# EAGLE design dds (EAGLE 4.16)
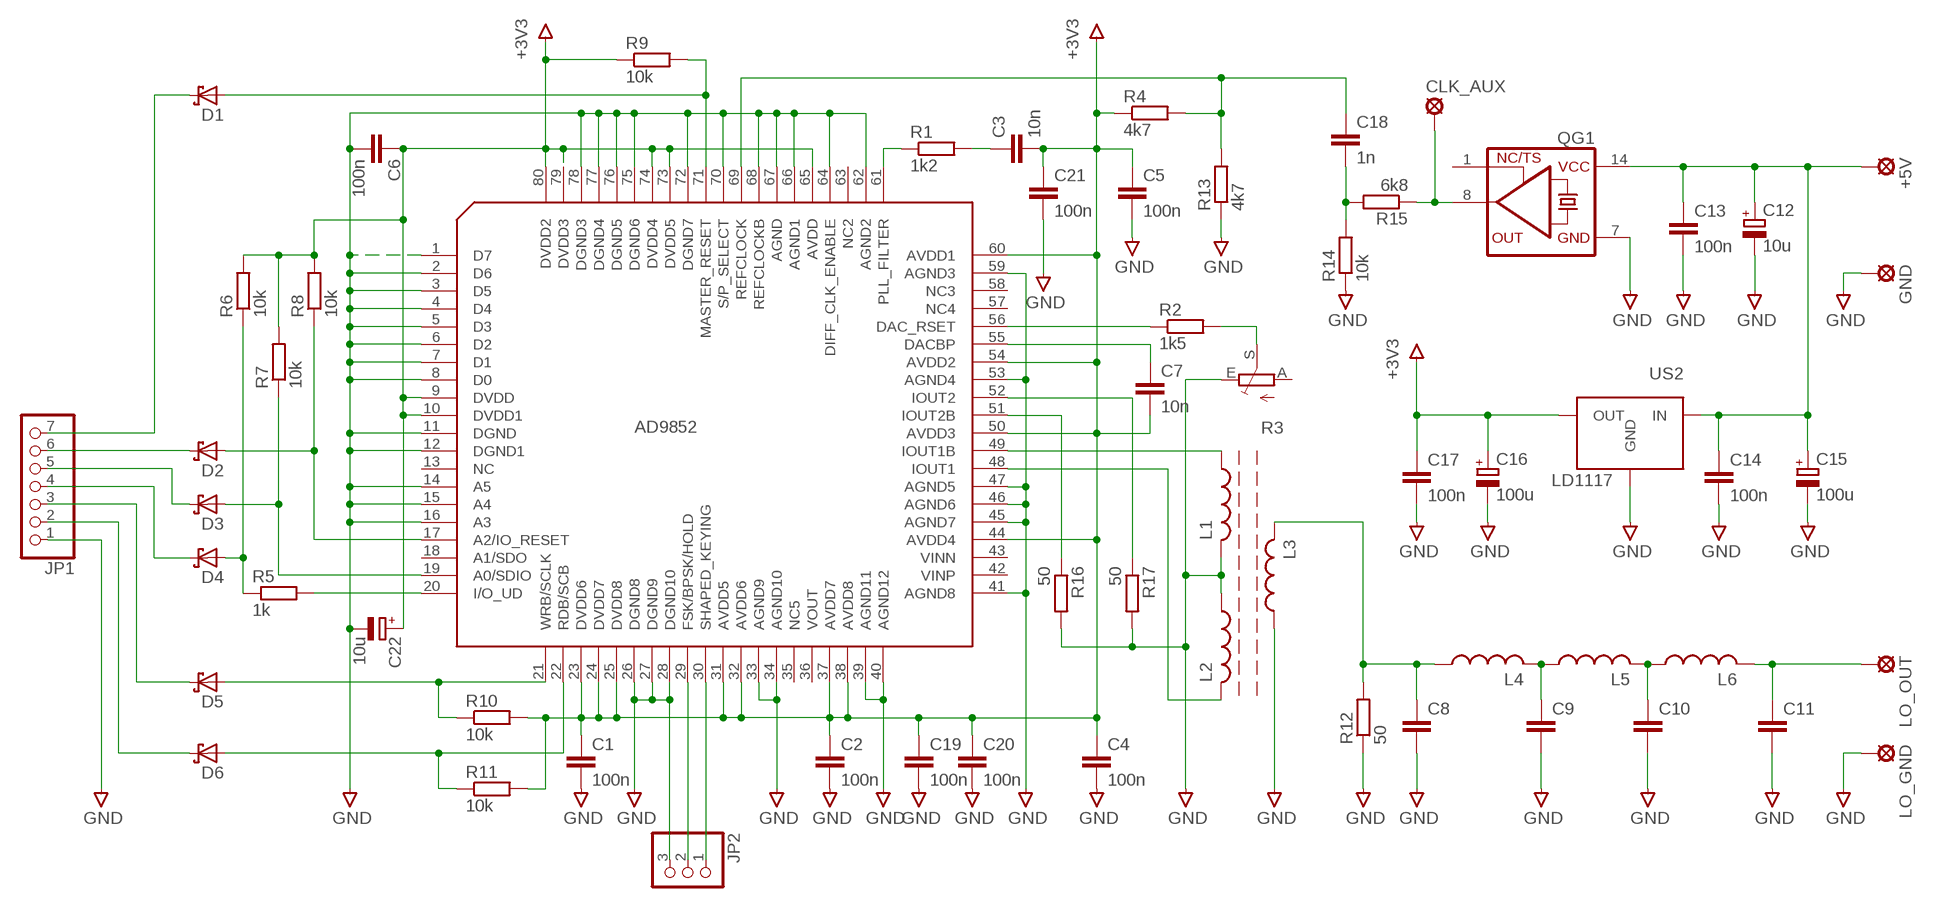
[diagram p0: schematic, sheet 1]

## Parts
+5V  LSP10  [LSP10]
C1  100n  C-EUC0805K  [C0805K]
C2  100n  C-EUC0805K  [C0805K]
C3  10n  C-EUC0805K  [C0805K]
C4  100n  C-EUC0805K  [C0805K]
C5  100n  C-EUC0805K  [C0805K]
C6  100n  C-EUC0805K  [C0805K]
C7  10n  C-EUC0805K  [C0805K]
C8  C-EU025-030X050  [C025-030X050]
C9  C-EU025-030X050  [C025-030X050]
C10  C-EU025-030X050  [C025-030X050]
C11  C-EU025-030X050  [C025-030X050]
C12  10u  CPOL-EUB45181A  [B45181A]
C13  100n  C-EU050-035X075  [C050-035X075]
C14  100n  C-EU050-035X075  [C050-035X075]
C15  100u  CPOL-EUB45181B  [B45181B]
C16  100u  CPOL-EUB45181B  [B45181B]
C17  100n  C-EU050-035X075  [C050-035X075]
C18  1n  C-EU025-030X050  [C025-030X050]
C19  100n  C-EUC0805K  [C0805K]
C20  100n  C-EUC0805K  [C0805K]
C21  100n  C-EUC0805K  [C0805K]
C22  10u  CPOL-EUB45181A  [B45181A]
CLK_AUX  LSP10  [LSP10]
D1  BAT42  [DO35-10]
D2  BAT42  [DO35-10]
D3  BAT42  [DO35-10]
D4  BAT42  [DO35-10]
D5  BAT42  [DO35-10]
D6  BAT42  [DO35-10]
GND  LSP10  [LSP10]
JP1  PINHD-1X7  [1X07]
JP2  PINHD-1X3  [1X03]
L1  L-US0204/5  [0204/5]
L2  L-US0204/5  [0204/5]
L3  L-US0204/5  [0204/5]
L4  L-US0204/5  [0204/5]
L5  L-US0204/5  [0204/5]
L6  L-US0204/5  [0204/5]
LO_GND  LSP10  [LSP10]
LO_OUT  LSP10  [LSP10]
QG1  XO-14  [DIL14S]
R1  1k2  R-EU_R1210  [R1210]
R2  1k5  R-EU_0207/12  [0207/12]
R3  TRIM_EU-CA6H  [CA6H]
R4  4k7  R-EU_0207/12  [0207/12]
R5  1k  R-EU_0207/12  [0207/12]
R6  10k  R-EU_0207/12  [0207/12]
R7  10k  R-EU_0207/12  [0207/12]
R8  10k  R-EU_0207/12  [0207/12]
R9  10k  R-EU_0207/12  [0207/12]
R10  10k  R-EU_0207/12  [0207/12]
R11  10k  R-EU_0207/12  [0207/12]
R12  50  R-EU_0207/12  [0207/12]
R13  4k7  R-EU_0207/12  [0207/12]
R14  10k  R-EU_0207/12  [0207/12]
R15  6k8  R-EU_0207/12  [0207/12]
R16  50  R-EU_0207/12  [0207/12]
R17  50  R-EU_0207/12  [0207/12]
U$1  AD9852  [SQ-80]
US2  LD1117  [TO-220]

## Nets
GND: C1.2 C2.2 C4.2 C5.2 C6.2 C8.2 C9.2 C10.2 C11.2 C12.- C13.2 C14.2 C15.- C16.- C17.2 C19.2 C20.2 C21.2 C22.- GND.MP JP1.1 JP2.3 L1.2 L2.1 L3.1 LO_GND.MP QG1.7(GND) R3.E R12.1 R13.1 R14.1 R16.2 R17.2 U$1.1(D7) U$1.2(D6) U$1.3(D5) U$1.4(D4) U$1.5(D3) U$1.6(D2) U$1.7(D1) U$1.8(D0) U$1.11(DGND) U$1.12(DGND1) U$1.14(A5) U$1.15(A4) U$1.16(A3) U$1.26(DGND8) U$1.27(DGND9) U$1.28(DGND10) U$1.33(AGND9) U$1.34(AGND10) U$1.39(AGND11) U$1.40(AGND12) U$1.41(AGND8) U$1.45(AGND7) U$1.46(AGND6) U$1.47(AGND5) U$1.53(AGND4) U$1.59(AGND3) U$1.62(AGND2) U$1.64(DIFF_CLK_ENABLE) U$1.66(AGND1) U$1.67(AGND) U$1.68(REFCLOCKB) U$1.70(S/P_SELECT) U$1.72(DGND7) U$1.75(DGND6) U$1.76(DGND5) U$1.77(DGND4) U$1.78(DGND3) US2.1(GND)
N$1: C7.1 U$1.55(DACBP)
N$2: L1.1 U$1.49(IOUT1B)
N$3: L2.2 U$1.48(IOUT1)
N$4: R2.1 U$1.56(DAC_RSET)
N$5: C3.1 R1.2
N$6: R1.1 U$1.61(PLL_FILTER)
N$7: R2.2 R3.S
N$8: R5.2 U$1.20(I/O_UD)
N$9: D1.A R9.2 U$1.71(MASTER_RESET)
N$10: D5.A R10.1 U$1.21(WRB/SCLK)
N$11: D6.A R11.1 U$1.22(RDB/SCB)
N$12: D2.A R8.1 U$1.17(A2/IO_RESET)
N$13: D3.A R7.1 U$1.19(A0/SDIO)
N$14: D4.A R5.1 R6.1
N$15: C8.1 L3.2 L4.1 R12.2
N$16: D1.C JP1.7
N$17: D2.C JP1.6
N$18: D3.C JP1.5
N$19: D4.C JP1.4
N$20: D5.C JP1.3
N$21: D6.C JP1.2
N$22: JP2.1 U$1.30(SHAPED_KEYING)
N$23: JP2.2 U$1.29(FSK/BPSK/HOLD)
N$24: C9.1 L4.2 L5.1
N$25: C10.1 L5.2 L6.1
N$26: C11.1 L6.2 LO_OUT.MP
N$27: +5V.MP C12.+ C13.1 C14.1 C15.+ QG1.14(VCC) US2.3(IN)
N$28: C18.1 R4.2 R13.2 U$1.69(REFCLOCK)
N$29: C18.2 R14.2 R15.2
N$30: CLK_AUX.MP QG1.8(OUT) R15.1
N$32: R16.1 U$1.51(IOUT2B)
N$33: R17.1 U$1.52(IOUT2)
N$51: C1.1 C2.1 C3.2 C4.1 C5.1 C6.1 C7.2 C16.+ C17.1 C19.1 C20.1 C21.1 C22.+ R4.1 R6.2 R7.2 R8.2 R9.1 R10.2 R11.2 U$1.9(DVDD) U$1.10(DVDD1) U$1.23(DVDD6) U$1.24(DVDD7) U$1.25(DVDD8) U$1.31(AVDD5) U$1.32(AVDD6) U$1.37(AVDD7) U$1.38(AVDD8) U$1.44(AVDD4) U$1.50(AVDD3) U$1.54(AVDD2) U$1.60(AVDD1) U$1.65(AVDD) U$1.73(DVDD5) U$1.74(DVDD4) U$1.79(DVDD3) U$1.80(DVDD2) US2.2(OUT) ; supply symbol labelled +3V3
Unconnected: QG1.1(TS) R3.A U$1.13(NC) U$1.18(A1/SDO) U$1.35(NC5) U$1.36(VOUT) U$1.42(VINP) U$1.43(VINN) U$1.57(NC4) U$1.58(NC3) U$1.63(NC2)

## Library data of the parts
+5V CLK_AUX GND LO_GND LO_OUT = solpad:LSP10: SOLDER PAD
C1-C7 C19-C21 = rcl-2:C-EU: CAPACITOR, European symbol
C8-C11 C13 C14 C17 C18 = rcl:C-EU: CAPACITOR, European symbol
C12 C15 C16 C22 = rcl:CPOL-EU: POLARIZED CAPACITOR, European symbol
D1-D6 = diode:BAT42: DIODE
JP1 = pinhead:PINHD-1X7: PIN HEADER
JP2 = pinhead:PINHD-1X3: PIN HEADER
L1-L6 = rcl:L-US: INDUCTOR, American symbol
QG1 = crystal:XO-: CRYSTAL
R1 = transceiver:R-EU_: RESISTOR, European symbol
R2 R4-R17 = rcl:R-EU_: RESISTOR, European symbol
R3 = pot:TRIM_EU-: POTENTIOMETER
U$1 = transceiver:AD9852
US2 = transceiver:LD1117

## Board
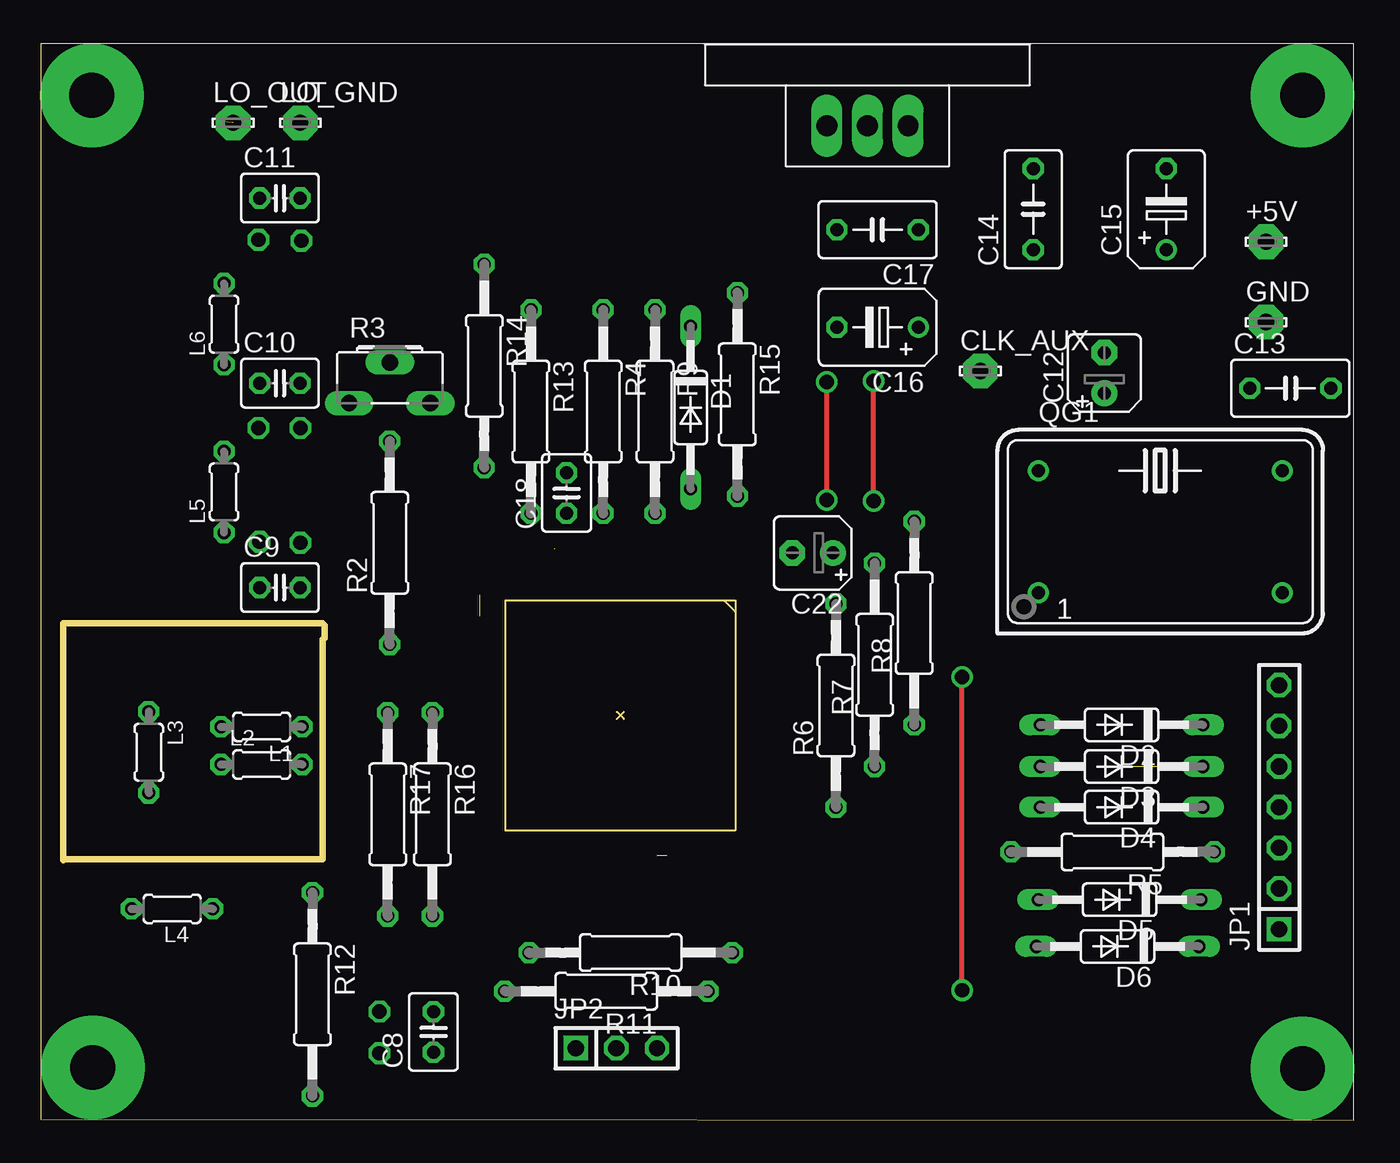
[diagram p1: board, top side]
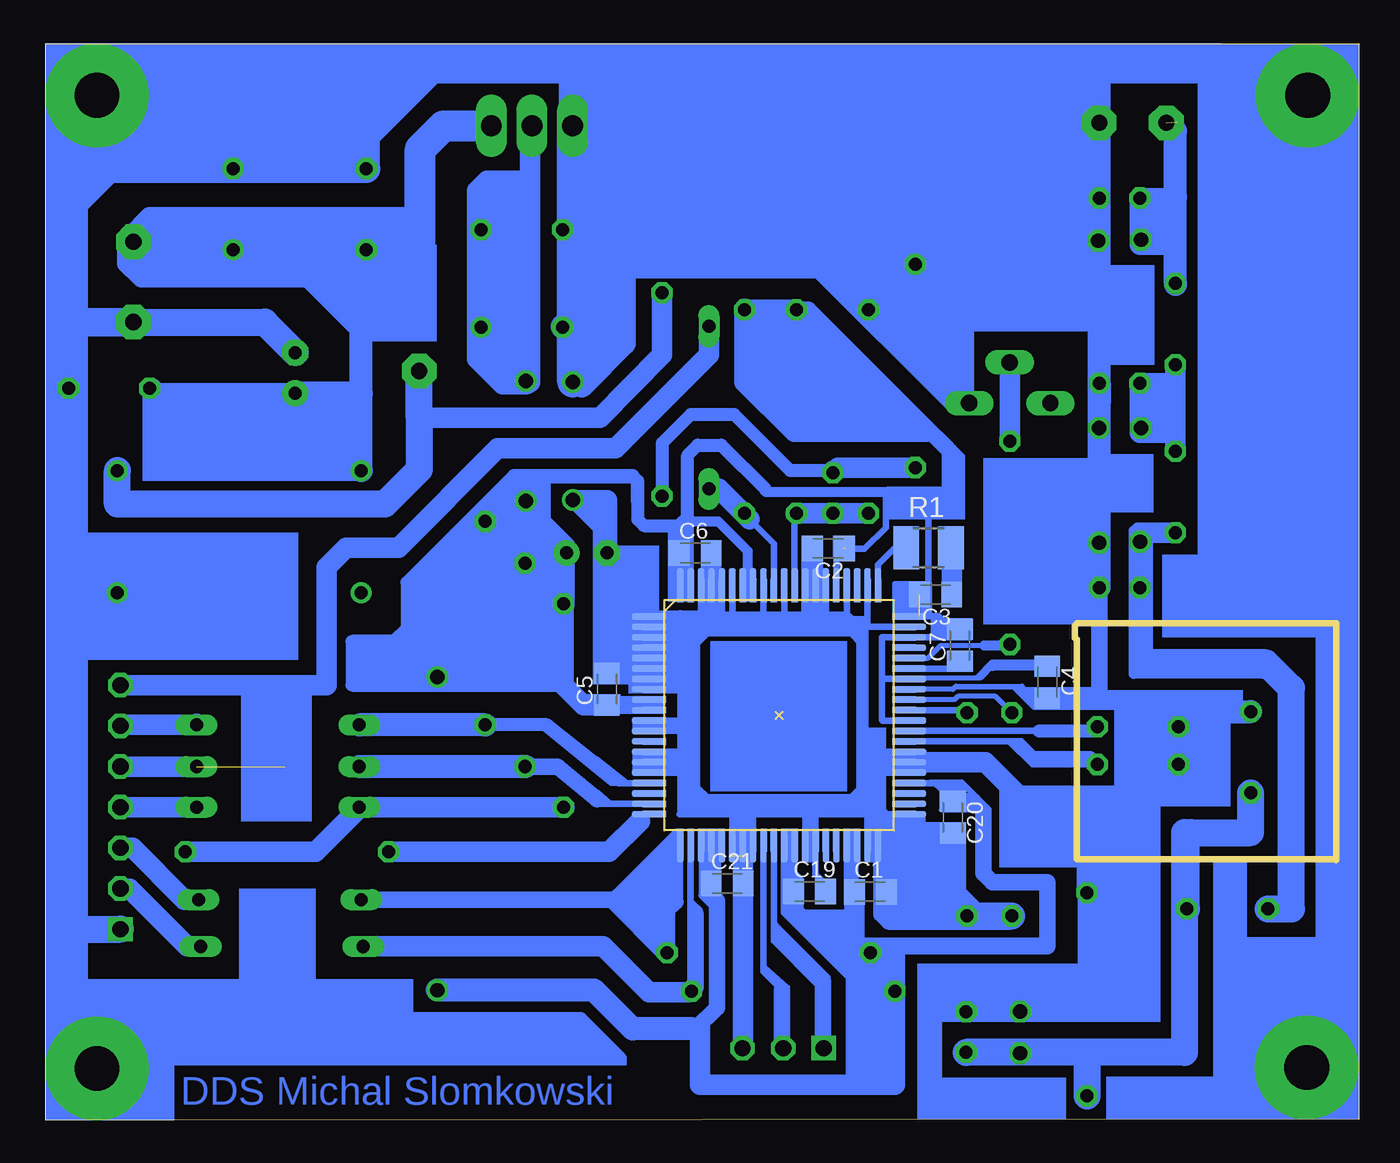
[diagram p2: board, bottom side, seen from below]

Size 82.03 x 67.24 mm. Coordinates in mm from the lower left corner, seen from the top.
Outline: 17.61,30.03 17.61,29.97
Outline: 17.61,29.97 17.61,16.31 1.49,16.31 1.42,16.25 1.42,31.05 17.61,31.05 17.74,30.92 17.74,30.09 17.61,29.97
Outline: 0,0.06 82.03,0 82.03,67.24 0,67.24 0,0.06
Copper layers (1*16): Top 0.035mm / dielectric 1.5mm / Bottom 0.035mm
Design rules "default": minimum track width 10mil, minimum drill 24mil, track to track 8mil, track to pad 8mil, pad to pad 8mil, via to via 8mil, smd to smd 8mil, copper to edge 40mil, drill to drill 8mil, minimum pad ring 10mil, minimum via ring 8mil, stop-mask expansion 4mil, vias tented up to drill 0mil, thermal gap 10mil

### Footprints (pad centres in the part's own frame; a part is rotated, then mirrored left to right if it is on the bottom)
LSP10 = drill 1.016 pad 2.159 octagon: MP 0,0
C0805K = smd 1.3 x 1.6: 1 -1,0; 2 1,0
C025-030X050 = drill 0.813 octagon: 1 -1.27,0; 2 1.27,0
B45181A = drill 0.813 pad 1.6 round: + -1.27,0 | drill 0.813 pad 1.6 octagon: - 1.27,0
C050-035X075 = drill 0.813 octagon: 1 -2.54,0; 2 2.54,0
B45181B = drill 0.813 round: + -2.54,0 | drill 0.813 octagon: - 2.54,0
DO35-10 = drill 0.813 long: A 5.08,0; C -5.08,0
1X07 = drill 1.016 square: 1 -7.62,0 | drill 1.016 octagon: 2 -5.08,0; 3 -2.54,0; 4 0,0; 5 2.54,0; 6 5.08,0; 7 7.62,0
1X03 = drill 1.016 square: 1 -2.54,0 | drill 1.016 octagon: 2 0,0; 3 2.54,0
0204/5 = drill 0.813 octagon: 1 -2.54,0; 2 2.54,0
DIL14S = drill 0.813 round: 1 -7.62,-3.81; 7 7.62,-3.81; 8 7.62,3.81; 14 -7.62,3.81
R1210 = smd 1.6 x 2.7: 1 -1.4,0; 2 1.4,0
0207/12 = drill 0.813 octagon: 1 -6.35,0; 2 6.35,0
CA6H = drill 1.016 long: A -2.54,0; E 2.54,0; S 0,2.54
SQ-80 = smd 0.813 x 0.406 bottom: 1 5.85,9.75; 2 5.85,9.1; 3 5.85,8.45; 4 5.85,7.8; 5 5.85,7.15; 6 5.85,6.5; 7 5.85,5.85; 8 5.85,5.2; 9 5.85,4.55; 10 5.85,3.9; 11 5.85,3.25; 12 5.85,2.6; 13 5.85,1.95; 14 5.85,1.3; 15 5.85,0.65; 16 5.85,0; 17 5.85,-0.65; 18 5.85,-1.3; 19 5.85,-1.95; 20 5.85,-2.6; 41 -11.7,-2.6; 42 -11.7,-1.95; 43 -11.7,-1.3; 44 -11.7,-0.65; 45 -11.7,0; 46 -11.7,0.65; 47 -11.7,1.3; 48 -11.7,1.95; 49 -11.7,2.6; 50 -11.7,3.25; 51 -11.7,3.9; 52 -11.7,4.55; 53 -11.7,5.2; 54 -11.7,5.85; 55 -11.7,6.5; 56 -11.7,7.15; 57 -11.7,7.8; 58 -11.7,8.45; 59 -11.7,9.1; 60 -11.7,9.75; P$1 -11.05,-2.6; P$2 -11.05,9.75; P$3 -10.4,9.75; P$22 -10.4,9.1; P$23 -10.4,8.45; P$25 -11.05,9.1; P$26 -11.05,8.45; P$27 -10.4,7.8; P$28 -11.05,7.15; P$29 -10.4,6.5; P$30 -10.4,5.85; P$31 -11.05,5.2; P$32 -10.4,4.55; P$33 -10.4,3.9; P$34 -10.4,3.25; P$35 -10.4,2.6; P$36 -10.4,1.95; P$37 -10.4,1.3; P$38 -10.4,0.65; P$39 -10.4,0; P$40 -10.4,-0.65; P$41 -10.4,-1.3; P$42 -10.4,-1.95; P$43 -10.4,-2.6; P$44 -11.05,7.8; P$45 -11.05,6.5; P$46 -10.4,7.15; P$47 -11.05,5.85; P$48 -10.4,5.2; P$49 -11.05,4.55; P$50 -11.05,3.9; P$51 -11.05,3.25; P$52 -11.05,2.6; P$53 -11.05,1.95; P$54 -11.05,1.3; P$55 -11.05,0.65; P$56 -11.05,0; P$57 -11.05,-0.65; P$58 -11.05,-1.3; P$59 -11.05,-1.95; P$121 4.55,-2.6; P$122 4.55,-1.95; P$123 4.55,-1.3; P$124 5.2,-2.6; P$125 5.2,-1.95; P$126 5.2,-1.3; P$127 4.55,-0.65; P$128 5.2,-0.65; P$129 4.55,0; P$130 5.2,0; P$131 4.55,0.65; P$132 5.2,0.65; P$133 4.55,1.3; P$134 5.2,1.3; P$135 4.55,1.95; P$136 5.2,1.95; P$137 4.55,2.6; P$138 5.2,2.6; P$139 4.55,3.25; P$140 5.2,3.25; P$141 4.55,3.9; P$142 5.2,3.9; P$143 4.55,4.55; P$144 5.2,4.55; P$145 4.55,5.2; P$146 5.2,5.2; P$147 4.55,5.85; P$148 5.2,5.85; P$149 5.2,6.5; P$150 4.55,6.5; P$151 4.55,7.15; P$152 5.2,7.15; P$153 5.2,7.8; P$154 4.55,7.8; P$155 4.55,8.45; P$156 5.2,8.45; P$157 5.2,9.1; P$158 4.55,9.1; P$159 4.55,9.75; P$160 5.2,9.75 | smd 0.406 x 0.813 bottom: 21 3.25,-5.2; 22 2.6,-5.2; 23 1.95,-5.2; 24 1.3,-5.2; 25 0.65,-5.2; 26 0,-5.2; 27 -0.65,-5.2; 28 -1.3,-5.2; 29 -1.95,-5.2; 30 -2.6,-5.2; 31 -3.25,-5.2; 32 -3.9,-5.2; 33 -4.55,-5.2; 34 -5.2,-5.2; 35 -5.85,-5.2; 36 -6.5,-5.2; 37 -7.15,-5.2; 38 -7.8,-5.2; 39 -8.45,-5.2; 40 -9.1,-5.2; 61 -9.1,12.35; 62 -8.45,12.35; 63 -7.8,12.35; 64 -7.15,12.35; 65 -6.5,12.35; 66 -5.85,12.35; 67 -5.2,12.35; 68 -4.55,12.35; 69 -3.9,12.35; 70 -3.25,12.35; 71 -2.6,12.35; 72 -1.95,12.35; 73 -1.3,12.35; 74 -0.65,12.35; 75 0,12.35; 76 0.65,12.35; 77 1.3,12.35; 78 1.95,12.35; 79 2.6,12.35; 80 3.25,12.35; P$4 -9.1,-3.9; P$5 -8.45,-3.9; P$6 -7.8,-3.9; P$7 -7.15,-3.9; P$8 -6.5,-3.9; P$9 -5.85,-3.9; P$10 -5.2,-3.9; P$11 -4.55,-3.9; P$12 -3.9,-3.9; P$13 -3.25,-3.9; P$14 -2.6,-3.9; P$15 -1.95,-3.9; P$16 -1.3,-3.9; P$17 -0.65,-3.9; P$18 0,-3.9; P$19 0.65,-3.9; P$20 1.3,-3.9; P$21 1.95,-3.9; P$24 2.6,-3.9; P$60 3.25,-3.9; P$81 -9.1,-4.55; P$82 -8.45,-4.55; P$83 -7.8,-4.55; P$84 -7.15,-4.55; P$85 -6.5,-4.55; P$86 -5.85,-4.55; P$87 -5.2,-4.55; P$88 -4.55,-4.55; P$89 -3.9,-4.55; P$90 -3.25,-4.55; P$91 -2.6,-4.55; P$92 -1.95,-4.55; P$93 -1.3,-4.55; P$94 -0.65,-4.55; P$95 0,-4.55; P$96 0.65,-4.55; P$97 1.3,-4.55; P$98 1.95,-4.55; P$99 2.6,-4.55; P$100 3.25,-4.55; P$181 3.25,11.05; P$182 2.6,11.05; P$183 1.95,11.05; P$184 3.25,11.7; P$185 2.6,11.7; P$186 1.95,11.7; P$187 1.3,11.7; P$188 0.65,11.7; P$189 0.65,11.05; P$190 1.3,11.05; P$191 0,11.7; P$192 0,11.05; P$193 -0.65,11.7; P$194 -0.65,11.05; P$195 -1.3,11.7; P$196 -1.3,11.05; P$197 -1.95,11.7; P$198 -1.95,11.05; P$199 -2.6,11.7; P$200 -2.6,11.05; P$201 -3.25,11.7; P$202 -3.25,11.05; P$203 -3.9,11.7; P$204 -3.9,11.05; P$205 -4.55,11.7; P$206 -4.55,11.05; P$207 -5.2,11.7; P$208 -5.2,11.05; P$209 -5.85,11.7; P$210 -5.85,11.05; P$211 -6.5,11.7; P$212 -6.5,11.05; P$213 -7.15,11.7; P$214 -7.15,11.05; P$215 -7.8,11.7; P$216 -7.8,11.05; P$217 -8.45,11.7; P$218 -8.45,11.05; P$219 -9.1,11.7; P$220 -9.1,11.05; P$224 -7.15,12.35; P$226 -6.5,12.35; P$228 -5.85,12.35; P$230 -5.2,12.35; P$233 -3.9,12.35; P$235 -3.25,12.35
TO-220 = drill 1.3 long: 1 -10.16,7.62; 2 -7.62,7.62; 3 -5.08,7.62

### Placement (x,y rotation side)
+5V  76.54,54.86 0 top
C1  30.52,14.26 0 bottom
C2  33.14,35.71 180 bottom
C3  26.44,32.82 180 bottom
C4  19.46,27.36 270 bottom
C5  46.97,26.93 90 bottom
C6  41.46,35.42 0 bottom
C7  24.92,29.66 90 bottom
C8  24.54,5.52 90 top
C9  14.95,33.27 0 top
C10  14.95,46.03 0 top
C11  14.95,57.59 0 top
C12  66.45,46.67 90 top
C13  78.07,45.72 0 top
C14  62,56.89 90 top
C15  70.32,56.89 90 top
C16  52.29,49.52 180 top
C17  52.29,55.62 180 top
C18  32.86,39.17 90 top
C19  34.32,14.28 0 bottom
C20  25.36,18.92 270 bottom
C21  39.46,14.79 0 bottom
C22  48.22,35.43 180 top
CLK_AUX  58.7,46.79 0 top
D1  40.6,44.51 270 top
D2  67.53,24.7 180 top
D3  67.53,22.09 180 top
D4  67.53,19.55 180 top
D5  67.4,13.77 180 top
D6  67.27,10.85 180 top
GND  76.54,49.84 0 top
JP1  77.37,19.55 90 top
JP2  35.97,4.5 0 top
L1  13.8,24.57 180 top
L2  13.8,22.22 0 top
L3  6.76,22.98 270 top
L4  8.22,13.2 180 top
L5  11.46,39.24 90 top
L6  11.46,49.72 90 top
LO_GND  16.22,62.29 0 top
LO_OUT  12.03,62.29 0 top
QG1  69.94,36.76 0 top
R1  26.89,35.75 0 bottom
R2  21.81,36.06 90 top
R3  21.81,44.79 0 top
R4  35.14,44.25 270 top
R5  66.95,16.76 180 top
R6  49.68,25.9 90 top
R7  52.1,28.44 90 top
R8  54.57,31.05 90 top
R9  38.38,44.25 270 top
R10  36.86,10.47 180 top
R11  35.33,8.06 180 top
R12  16.98,7.87 270 top
R13  30.63,44.25 270 top
R14  27.71,47.11 270 top
R15  43.52,45.33 270 top
R16  24.47,19.11 270 top
R17  21.68,19.11 270 top
U$1  39.14,21.71 0 top
US2  59.27,54.48 0 top

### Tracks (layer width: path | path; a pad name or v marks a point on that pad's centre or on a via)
GND  (via drill 0.9)  (1 unrouted)
  Top 0.305: v49.11,38.73 v49.11,46.1
  Bottom 0.254: 21.68,27.05 21.62,27.05 20.34,25.78 15.2,25.78
  Bottom 0.305: 25.37,26.91 25.23,27.05 21.68,27.05 21.49,27.05 21.43,27.05 | 25.37,26.91 U$1.53 | 25.37,26.91 25.17,27.11 21.04,27.11 20.15,26.22 12.73,26.22 | 11.27,24.76 L1.2 L2.1 11.27,22.09
  Bottom 0.406: 29.81,22.41 29.81,21.71 | 29.81,22.41 30.89,22.92 | 30.89,22.92 30.89,26.92 30.89,26.79 | 29.81,21.71 29.81,19.11 | 29.81,19.11 27.58,19.11 U$1.41 27.64,19.11 27.78,18.98 27.78,18.28 27.41,17.92 C20.2 | 29.81,21.71 U$1.45 | 30.89,22.92 29.49,22.98 29.65,23.01 U$1.47 | 29.81,22.41 29.74,22.41 29.69,22.36 27.97,22.36 U$1.46 | 29.81,19.11 29.74,19.11 | 29.81,19.11 30.06,19.11 | 30.06,19.11 30.7,19.11 | 42.38,19.11 42.44,19.11 | 42.38,19.11 42.38,21.71 | 42.38,21.71 42.38,22.41 | 42.38,22.41 42.38,23.05 | 42.38,23.05 42.38,24.32 | 42.38,24.32 42.38,25.01 | 42.38,25.01 42.38,26.92 | 42.38,26.92 42.38,27.62 | 42.38,27.62 42.38,28.19 | 42.38,28.19 42.38,28.82 | 42.38,28.82 42.38,29.52 | 42.38,29.52 42.38,30.16 | 42.38,30.16 42.38,30.79 | 42.38,30.79 42.38,31.43 42.32,31.49 42.32,31.55 | U$1.1 42.41,31.46 42.32,31.55 | U$1.2 42.4,30.81 42.38,30.79 | U$1.3 42.39,30.16 42.38,30.16 | U$1.4 42.39,29.51 42.38,29.52 | U$1.5 42.42,28.86 42.38,28.82 | U$1.6 44.48,28.21 42.4,28.21 42.38,28.19 | U$1.7 42.44,27.56 42.38,27.62 | U$1.8 42.39,26.91 42.38,26.92 | U$1.11 42.43,24.96 42.38,25.01 | U$1.12 42.38,24.31 42.38,24.32 | U$1.14 42.41,23.01 42.38,23.05 | U$1.15 42.43,22.36 42.38,22.41 | 42.38,21.71 U$1.16 | U$1.40 30.04,19.09 30.06,19.11 | 30.7,19.11 33.93,19.11 | 33.93,19.11 37.74,19.11 | 37.74,19.11 38.44,19.11 | 38.44,19.11 39.08,19.11 | 39.08,19.11 42.38,19.11 | U$1.34 33.93,16.51 33.93,19.11 | U$1.39 30.69,19.1 30.7,19.11 | 30.7,19.11 34.51,19.11 34.57,19.04 34.57,16.44 34.59,16.46 | 34.59,16.46 U$1.33 | 42.32,31.55 41.05,31.55 | 41.05,31.55 40.41,31.55 | 40.41,31.55 39.78,31.55 | 39.78,31.55 39.2,31.55 | 39.2,31.55 39.14,31.55 U$1.75 39.14,34.16
  Bottom 0.406: U$1.62 30.69,32.07 30.7,32.06 30.7,31.05 31.2,31.17 | 31.2,31.17 31.33,31.05 31.97,31.55 | 39.2,31.55 37.17,31.55 | 37.17,31.55 35.9,31.55 | 35.9,31.55 34.57,31.55 | 34.57,31.55 33.93,31.55 | 33.93,31.55 33.3,31.55 | 33.3,31.55 31.97,31.55 | U$1.64 31.99,31.58 31.97,31.55 | U$1.66 33.29,31.56 33.3,31.55 | U$1.67 33.94,31.56 33.93,31.55 | U$1.68 34.59,31.58 34.57,31.55 | U$1.72 37.19,31.57 37.17,31.55 | U$1.70 35.89,31.57 35.9,31.55 | U$1.78 41.09,31.6 41.05,31.55 | U$1.77 40.44,32.06 40.44,31.58 40.41,31.55 | U$1.76 39.79,31.57 39.78,31.55 | U$1.26 39.14,19.04 39.08,19.11 | 38.49,18.47 38.49,19.06 38.44,19.11 | U$1.28 37.84,19.01 37.74,19.11 | 34.59,16.46 34.08,16.46 33.93,16.31 33.93,15.36 33.36,14.79 33.36,14.35 33.3,14.28 C19.2 | U$1.59 30.91,30.81 31.2,31.17 | 27.46,21.84 27.46,21.97 | 20.41,26.35 20.73,26.35 21.43,27.05 | 21.49,27.05 20.47,26.03 20.03,26.03
  Bottom 0.61: U$1.46 27.44,21.86 27.46,21.84 | C4.2 19.64,26.36 19.65,26.35 20.41,26.35
  Bottom 0.813: C2.2 34.14,35.73 34.12,35.75 33.94,35.56 U$1.67 | C1.2 29.74,14.26 29.74,17.78 29.74,19.11
  Bottom 1.016: 44.48,28.21 44.48,28 44.55,27.93 C5.2 | 16.22,26.36 11.72,26.36 11.33,25.2 | 16.22,26.36 C4.2 | 16.22,26.36 16.22,26.35 | 16.22,26.36 C9.2
  Bottom 1.27: 40.44,32.06 40.35,32.06 40.46,32.17 C6.2 | 38.49,18.47 38.51,18.47 38.46,18.43 C21.2 38.46,4.46 | C22.- 46.95,38.73 48.98,38.73 | 48.98,38.73 v49.11,38.73 | 38.46,4.46 JP2.3 | 38.46,4.46 38.44,4.44 | 49.11,55.56 49.17,55.56 49.24,55.62 C17.2 | 49.11,49.33 49.37,49.33 49.56,49.52 C16.- | 17.23,20.25 16.98,20.25 R12.1 16.92,14.22 16.85,14.16 16.92,14.09 16.92,6.79 v21.17,6.79 C8.2 | 17.23,20.25 21.23,20.25 23.33,22.35 27.9,22.35 27.97,22.28 27.97,22.36 | 11.27,20.51 11.27,20.25 17.17,20.25 17.23,20.19 17.23,20.25 | L1.2 11.27,24.82 11.33,24.89 10.69,25.52 10.38,25.52 | 48.98,38.73 48.86,38.73 47.02,36.89
  Bottom 1.422: C16.- 49.75,49.59 | R13.1 30.63,50.67 24.75,44.79 R3.E 24.35,44.77 | L1.2 11.33,24.57 | 10.38,25.52 L3.1 | 10.76,24.63 11.33,25.2 | LO_GND.MP 16.28,62.29 16.22,62.23 C11.2 C10.2 | C10.2 16.22,44.76 | C9.2 v16.22,36.06 v16.22,43.24 C10.2 | 49.17,46.03 48.54,45.84 45.87,48.51 45.87,52.95 47.71,52.95 48.03,52.64 48.03,47.68 47.9,47.56 47.27,47.56 46.89,47.94 46.89,52.06 46.83,52.13
  Bottom 1.676: C22.- 46.95,28.57 45.36,28.57 45.05,28.89 45.02,28.86 U$1.5 | C13.2 80.61,36.06 | JP1.1 79.91,11.93 80.61,12.63 80.61,36.06 | QG1.7 80.54,32.95 80.61,36.06 | GND.MP 68.35,49.84 C12.- | C14.2 62,61.46 57.68,65.78 49.75,65.78 49.11,65.15 49.11,62.35 48.92,62.16 48.98,62.1 US2.1 | R14.1 28.66,54.29 30.63,54.29 | 30.63,54.29 48.98,54.29 49.11,56.07 | 30.63,54.29 30.63,50.67 | R17.2 R16.2 24.47,13.2 28.85,17.58 29.23,17.58 29.43,17.78 29.74,17.78 | L1.2 L2.1 11.27,20.51 | 10.76,24.63 10.38,24.63 11.27,24.76
  Bottom 1.778: 80.61,49.84 C13.2 | 80.61,49.84 80.61,56.95 78.13,59.43 C15.- C14.2 | 80.61,49.84 GND.MP
  Bottom 1.93: US2.1 49.11,56.07 49.11,55.56 49.11,49.33 v49.11,46.1
N$1
  Bottom 0.406: C7.1 25.11,28.69 25.36,28.76 25.26,28.21 U$1.55
N$2
  Bottom 0.406: U$1.49 19.97,24.31 19.96,24.32
  Bottom 0.813: L1.1 16.34,24.51 16.54,24.32 19.96,24.32
N$3
  Bottom 0.406: U$1.48 21.09,23.66 20.09,22.66
  Bottom 0.813: 20.09,22.66 16.79,22.66 L2.2
N$4
  Bottom 0.305: U$1.56 26.91,28.86 26.12,29.65 23.39,29.65
  Bottom 0.61: R2.1 21.87,29.71 21.93,29.65 23.39,29.65
N$5
  Bottom 1.016: 25.44,35.86 25.49,35.81 R1.2 | C3.1 25.44,35.86 | 25.44,35.86 25.43,35.87
N$6
  Bottom 0.406: U$1.61 30.04,34.69 28.98,35.75 R1.1 | R1.1 | R1.1 28.22,35.68
N$7
  Bottom 1.27: R3.S 21.77,47.33 21.74,47.3 21.81,47.24 R2.2
N$8
  Bottom 0.305: U$1.20 44.99,18.99 44.79,18.47
  Bottom 0.61: 44.79,18.47 44.92,18.66 45.49,18.28
  Bottom 1.27: R5.2 46.83,16.76 44.92,18.66
N$9
  Bottom 0.406: R9.2 38.12,37.59 36.54,36 U$1.71
  Bottom 1.27: R9.2 38.06,37.52 38.12,37.59 39.97,39.43 D1.A
N$10
  Bottom 0.406: U$1.21 42.39,13.95 43.2,13.65
  Bottom 1.016: R10.1 43.2,13.65 42.7,13.65 42.76,13.77 D5.A
N$11
  Bottom 0.406: U$1.22 41.74,12.82 41.43,12.89
  Bottom 1.016: 41.81,8.06 41.87,8 | R11.1 41.81,8.06 | 41.43,12.89 41.43,8.31 41.81,8.06
  Bottom 1.27: 41.87,8 44.35,8 47.21,10.85 D6.A
N$12
  Bottom 0.406: U$1.17 46.24,21.06 47.84,22.41
  Bottom 0.813: R8.1 50.7,24.7 47.84,22.41
  Bottom 1.422: R8.1 D2.A
N$13
  Bottom 0.406: U$1.19 47.42,19.76 47.59,20.06
  Bottom 1.016: 52.03,22.09 50.06,22.09 47.59,20.06
  Bottom 1.422: 52.03,22.09 R7.1 D3.A
N$14
  Bottom 1.27: R5.1 65.18,16.76 62.45,19.49 D4.A R6.1 49.62,19.55
N$15
  Bottom 1.676: L3.2 6.76,17.97 10.5,17.97 10.66,17.74 | 10.66,17.74 10.82,17.58 10.82,13.14 L4.1 | 16.85,4.25 10.88,4.25 10.88,17.97 10.66,17.74 | 16.85,4.25 C8.1 | 10.66,17.74 | R12.2 16.98,4.12 16.85,4.25
N$16
  Bottom 1.27: JP1.7 77.37,27.11 77.31,27.17 64.48,27.17 64.48,34.54 63.27,35.75 59.97,35.75 53.81,41.97 46.44,41.97 40.6,47.81 D1.C
N$17
  Bottom 1.27: D2.C 72.61,24.76 72.67,24.7 77.31,24.7
  Bottom 1.422: JP1.6 77.31,24.7
N$18  (1 unrouted)
  Bottom 1.27: JP1.5 D3.C
N$19
  Bottom 1.27: JP1.4 D4.C
N$20
  Bottom 1.27: JP1.3 76.61,17.01 73.37,13.77 D5.C
N$21
  Bottom 1.27: JP1.2 76.8,14.47 73.18,10.85 D6.C
N$22
  Bottom 0.406: U$1.30 36.54,11.75 35.2,10.41
  Bottom 1.016: 35.2,10.41 33.49,8.69 33.49,4.5 33.43,4.44 JP2.1
N$23
  Bottom 0.406: U$1.29 37.19,9.28 36.03,8.12
  Bottom 1.016: JP2.2 35.97,4.57 36.03,4.63 36.03,8.12
N$24  (via drill 0.9)
  Bottom 1.27: 13.49,28.57 13.49,36.57 C9.1 v13.68,36.13 13.68,36.7 L5.1
  Bottom 1.676: L4.2 4.22,13.2 4.22,26.98 5.8,28.57 13.49,28.57
N$25
  Bottom 1.27: L5.2 11.45,44.76 | 11.45,44.76 L6.1 | 11.45,44.76 11.52,46.03 C10.1 13.68,42.92 11.77,42.92
  Bottom 1.422: 11.77,42.92 12.73,43.87 12.73,44.25 12.6,44.38 12.6,45.14 12.54,45.21
N$26  (1 unrouted)
  Bottom 1.27: 11.45,57.65 11.45,57.59 C11.1 13.68,54.67 11.58,54.67 11.52,54.61 11.96,54.61 12.85,55.49 12.85,55.56 12.66,55.75 12.66,56.76
  Bottom 1.422: 11.45,52.19 L6.2 11.45,57.65 11.45,61.78 12.03,62.35 LO_OUT.MP
N$27
  Bottom 1.27: C14.1 62,54.41 62.32,54.1 | C13.1 75.4,45.72 75.08,45.4 66.32,45.4
  Bottom 1.422: 62.32,45.4 66.32,45.4 C12.+ | QG1.14 62.32,45.4 | 62.32,45.4 62.32,54.29 62.38,54.35
  Bottom 1.93: US2.3 57.17,62.1 58.64,60.64 58.64,54.35 C14.1 | C14.1 62.06,54.35 | C14.1 62.38,54.35 C15.+ 76.03,54.35 +5V.MP
N$28
  Bottom 0.406: U$1.69 35.24,37.87 35.2,37.9
  Bottom 1.27: R13.2 32.98,37.9 | 32.98,37.9 R4.2 | 32.98,37.9 35.2,37.9 C18.1
N$29
  Bottom 0.813: 32.86,40.57 35.52,40.57 39.02,44.06 41.75,44.06 43.52,42.29 R15.2 43.46,38.92
  Bottom 1.27: R14.2 32.54,40.76 32.79,40.51 | 32.79,40.51 C18.2 | 32.79,40.51 32.86,40.57
N$30
  Bottom 1.27: R15.1 43.52,47.81 47.4,43.87 58.7,43.87
  Bottom 1.676: CLK_AUX.MP 58.7,43.87 58.7,40.64 60.86,38.48 77.56,38.48 QG1.8
N$31  (via drill 2.8 pad 6.45)
  other vias: 3.26,3.3
N$32
  Bottom 0.406: U$1.51 24.63,25.61 R16.1
N$33
  Bottom 0.305: U$1.52 25.26,26.26 25.04,26.47 22.69,26.47 R17.1 21.62,25.4
  Bottom 0.406: R17.1 21.62,25.46
N$34  (via drill 2.8 pad 6.45)
  other vias: 3.2,64
N$35  (via drill 2.8 pad 6.45)
  other vias: 78.83,64
N$36  (via drill 2.8 pad 6.45)
  other vias: 78.83,3.23
N$37
  Bottom 0.305: 34.82,14.73 34.82,15.04 35.14,15.36
N$38
  Bottom 0.305: 41.11,16.44 41.11,14.03 40.35,13.27
N$39
  Bottom 0.305: 41.11,12.69 41.11,13.08 41.62,13.58
N$40
  Bottom 0.305: 42.38,13.46 43.08,12.76
N$41
  Bottom 0.813: 29.93,16.25 29.93,12.82 29.43,12.31 21.74,12.31 21.49,12.57
N$42
  Bottom 0.406: 35.9,17.97 35.9,12.95 32.92,9.96 29.36,9.96
N$43
  Bottom 0.406: 33.36,10.47 33.36,10.41 31.71,8.76 31.71,9.14 32.41,9.84
N$44
  Bottom 0.254: 35.65,8.31 37.11,9.58 35.9,8.25
N$45
  Bottom 0.254: 33.87,8.44 36.6,11.17 36.6,11.62 36.54,11.68 36.54,11.42 35.65,10.54
N$46
  Bottom 0.254: 33.11,8.95 36.41,12.25 36.41,11.93 36.35,11.93 35.27,10.85
N$47
  Bottom 0.406: 16.79,22.22 20.41,22.22 21.81,23.62 21.43,23.62 20.47,22.66
N$48
  Bottom 0.406: 16.66,26.86 20.92,26.86
N$49
  Bottom 0.254: 20.15,28.63 22.95,28.63 23.9,27.68
N$50
  Bottom 0.61: 5.99,27.87 14.06,27.87 14.06,36.83 13.87,37.02
N$51  (via drill 0.9)  (2 unrouted)
  Top 0.305: v57.56,8.12 v57.56,27.68 | v52.03,38.67 v52.03,46.16
  Bottom 0.254: U$1.38 31.33,16.51 31.65,16.19 31.65,16.06 | U$1.74 38.22,34.06 38.19,34.09 | 26.12,20.7 26.12,19.36 24.03,19.36
  Bottom 0.305: 44.73,25.97 44.99,26.23 | U$1.31 35.53,16.51 35.52,16.51 | 28.92,8.19 28.92,8.12 R11.2 | U$1.54 27.26,27.56 27.2,27.62 23.65,27.62 22.89,28.38 | 29.36,39.24 29.36,39.17 29.55,39.17
  Bottom 0.406: U$1.74 38.47,34.06 38.44,34.03 38.41,34.06 U$1.73 | U$1.79 41.74,34.03 41.75,34.03 41.78,34.06 U$1.80 | U$1.9 44.99,26.23 44.98,26.22 44.99,26.21 U$1.10 | 31.97,16.51 U$1.37 31.78,16.51 31.71,16.44 | U$1.38 31.97,16.51 | 31.97,16.51 31.97,16.57 | U$1.24 40.42,16.51 40.41,16.51 | U$1.24 U$1.23 | U$1.24 39.85,16.51 39.84,16.51 39.83,16.51 U$1.25 40.02,16.51 40.41,16.12 40.41,14.35 | C20.1 25.36,19.93 26.12,20.7 26.49,21.06 U$1.44 | 35.57,13.45 U$1.31 35.85,16.51 35.84,16.51 35.83,16.51 U$1.32 35.24,13.18 33.17,11.11 31.58,11.11 31.52,11.17 | 28.98,9.77 28.98,8.25 28.92,8.19 | U$1.60 26.22,31.46 25.55,30.79 | 25.55,30.79 25.11,30.79 24.97,30.66 C7.2 24.92,30.48 24.85,30.41 26.44,30.41 26.7,30.16 29.81,30.16 29.81,27.74 | 25.55,30.79 25.55,30.22 | U$1.54 29.8,27.56 29.81,27.55 29.81,27.74 | C3.2 27.46,32.82 27.46,32.95 26.89,33.52 26.89,38.98 | U$1.65 32.64,35.13 32.09,35.68 30.89,35.68 29.55,37.02 29.55,39.17 | U$1.50 29.75,24.96 29.81,25.01 29.81,27.74
  Bottom 0.61: 19.46,28.32 | C4.1 19.46,28.32 | 22.89,28.38 19.52,28.38 19.46,28.32 | 42.44,37.14 42.44,36.95 | U$1.80 42.41,34.06 42.44,34.03 42.46,34.05 C6.1 | 38.19,34.09 38.19,35.55 40.03,37.4 42.19,37.4 | 37.05,39.36 37.05,39.24 29.36,39.24 26.38,39.24 26.19,39.05 | 26.89,38.98 26.89,39.17
  Bottom 0.813: 49.94,27.17 62.89,27.17 62.89,29.9 60.29,29.9 59.46,30.73 59.46,33.59 52.79,40.25 45.36,40.25 45.05,39.94 45.05,38.6 | C1.1 31.65,14.26 31.65,16.06 | 35.52,16.51 35.52,14.54 35.27,14.28 | 35.27,14.28 35.2,14.22 35.33,14.09 | 35.27,14.28 C19.1 | 37.05,39.36 39.84,42.16 41.3,42.16 41.94,41.52 41.94,37.65 42.19,37.4 42.44,37.14 44.67,37.14 45.05,37.52 45.05,38.6 | 45.05,38.6 45.05,39.87 45.36,40.19 51.97,40.19 51.97,38.67 52.03,38.6 | 28.28,10.85 31.46,10.85 19.96,10.98 33.3,10.98
  Bottom 1.016: C5.1 46.95,25.9 46.89,25.97 44.73,25.97 | 40.41,14.35 40.41,14.03 40.09,13.71 40.09,7.04 41.43,5.71 41.17,5.2 | R9.1 34.38,50.6 25.55,41.78 25.55,39.05 26.19,39.05 26.89,38.98 27.01,38.98 | 25.36,19.93 24.09,19.93 23.46,19.3 23.46,15.43 22.89,14.85 19.46,14.85 19.46,10.85 28.28,10.85 28.85,10.85 28.98,9.77 | U$1.80 42.41,34.06 42.44,34.09 42.44,36.95
  Bottom 1.27: U$1.24 40.47,16.51 40.46,16.49 C21.1 | R9.1 R4.1 | R10.2 29.11,10.47 29.04,10.41 28.98,10.41 28.98,9.77 R11.2 28.98,2.22 41.17,2.22 41.17,5.2 41.17,5.77 | C5.1 48.44,25.93 49.68,27.17 49.68,27.68 | R6.2 49.62,32.25 49.68,32.19 49.68,27.68 | v57.56,27.68 49.68,27.68 | R7.2 52.03,34.73 52.03,35.43 | 52.03,35.43 52.03,37.4 | 52.03,35.43 52.09,35.43 52.03,35.36 49.68,35.36 | 52.03,37.4 R8.2 | 52.03,38.29 52.03,37.4 | 52.03,38.29 52.03,38.6 v52.03,38.67 | 35.33,14.09 35.33,13.01 33.3,10.98 | C1.1 31.52,14.41 31.52,11.17 | 49.56,35.49 49.56,35.81 52.03,38.29 | 52.03,57.02 52.03,46.35 51.78,46.1 51.78,62.03 51.65,62.16 US2.2
  Bottom 1.422: C22.+ 49.56,35.49 49.68,35.36 R6.2 | v57.56,8.12 47.78,8.12 45.36,5.71 41.55,5.71 41.49,5.65 41.43,5.71
  Bottom 1.676: 52.03,57.02 C17.1 54.83,49.65 | v52.03,46.16 53.3,46.16 54.83,47.68 54.83,49.65 | 54.83,49.65 C16.+
N$52
  Bottom 1.27: 51.84,58.67 54.45,58.67 55.08,58.03 55.08,47.56 53.49,45.97
N$53
  Bottom 1.27: 76.67,54.99 76.67,55.24 75.53,56.38 59.08,56.38 59.02,56.45 59.02,55.81 59.34,55.49 75.53,55.49
N$54
  Bottom 1.27: 76.92,54.8 76.92,53.53 76.03,52.64 65.62,52.64 62.51,49.52 62.51,50.67 65.49,53.65 63.97,53.65 62.7,52.38 64.67,52.38 65.88,53.59 75.78,53.59 76.03,53.34
N$55
  Bottom 0.813: 59.27,6.35 48.6,6.35 46.13,3.87
N$56
  Bottom 0.406: 50.89,24.51 46.7,21.08 45.81,21.08
N$57
  Bottom 0.406: 47.65,22.54 45.87,21.14
N$58
  Bottom 0.305: 28.98,31.55 28.98,33.52 26.82,33.52 26.82,31.55 26.76,31.49
N$59
  Bottom 0.254: 26.7,30.09 26.57,30.09 | 26.57,30.09 24.22,30.09 24.22,31.24 26.63,31.24 26.63,30.16 26.57,30.09
N$60
  Bottom 1.27: 38.38,50.67 38.38,46.1 35.27,42.98 27.01,42.98
N$61
  Bottom 0.406: 24.79,37.97 24.79,41.46 26.12,42.79
N$62
  Bottom 0.406: 47.59,20.44 46.83,19.81
N$63
  Bottom 1.016: 43.4,10.47 46.57,13.65 45.68,13.65 43.71,11.68 43.71,12.76 44.22,13.27
N$64
  Bottom 0.61: 42.63,17.9 46.44,14.09
N$65
  Bottom 0.61: 42.63,17.27 42.63,17.14 45.75,14.03 45.17,14.03 42.7,16.51 42.7,15.74 44.28,14.16 43.71,14.16 42.57,15.3 42.57,14.6 43.14,14.03
N$66
  Bottom 1.27: 24.66,45.08 24.66,49.97 24.73,50.03 25.43,50.03 25.62,49.84 25.62,46.48 25.68,46.41 25.87,46.41 26.82,47.37 26.82,49.27 26.63,49.46 27.27,49.46 28.16,48.57
N$67
  Bottom 1.27: 30.57,50.54 30.82,50.54 33.68,53.4 33.68,53.21 25.23,44.76
N$68
  Bottom 1.27: 32.73,53.53 32.73,53.34 31.33,51.94
N$69
  Bottom 0.406: 26.76,21.08 24.79,21.08 23.14,19.43
N$70
  Bottom 0.406: 26.12,20.89 26,20.89 25.68,20.57 24.73,20.57 24.66,20.63 24.85,20.82 25.74,20.82
N$71  (via drill 0.9)
  other vias: 21.17,4.19
N$72  (via drill 0.9)
  other vias: 13.61,54.99
N$73  (via drill 0.9)
  other vias: 16.28,54.92
N$74  (via drill 0.9)
  other vias: 13.61,43.24
(copper drawn outside any net)
  shapes: Bottom area x109

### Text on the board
Bottom: DDS Michal Slomkowski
